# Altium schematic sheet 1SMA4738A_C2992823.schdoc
size 127 x 101 mm
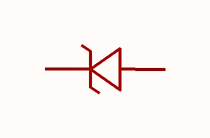
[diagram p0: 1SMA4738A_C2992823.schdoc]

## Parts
D?  1sma4738a  [SMA_L4.2-W2.6-LS5.1-RD]  (value not drawn)

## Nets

Not connected (* = marked no-connect by the designer): D? 1(K) 2(A)

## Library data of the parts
D? = 1sma4738a: 二极管配置:1个独立式;稳压值(标称值):8.2V;稳压值(范围):7.79V~8.67V;耗散功率(Pd):1W;; Manufacturer: MDD(辰达半导体); Symbol: 1SMA4738A_C2992823; AddInBom: yes; ModelId: 0bbbb6fb043b4d77ba3f63ca91d261ab; ModelTransform: 198.8185,102.362,0,0,0,0,0,0,0; Diode Configuration: 1个独立式; Zener Voltage(Nom): 8.2V; Reverse Leakage Current (Ir): 10uA@6V; Pd - Power Dissipation: 1W; Impedance(Zzt): 4.5Ω; Operating Junction Temperature Range: -55℃~+150℃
